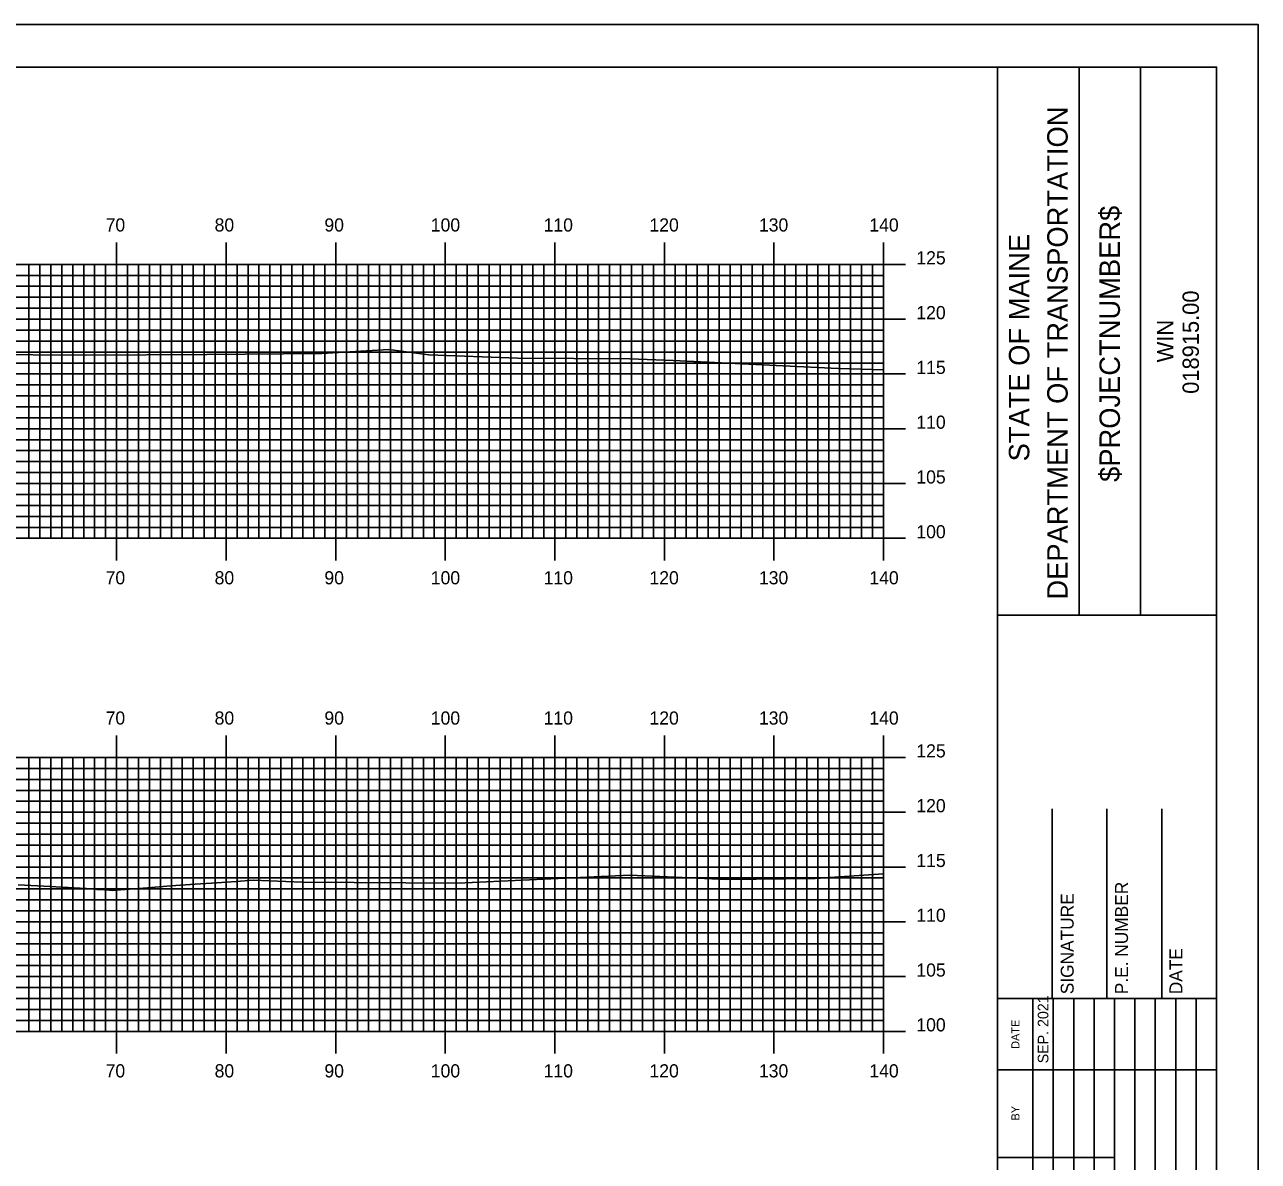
# Model space of a CAD drawing. Extents: x 1766513 to 1766856, y 442591 to 442811.
# Drawn here: x 1766740.5 to 1766853.1, y 442706.8 to 442810.5 of the extents above; entities that cross this region are included whole.
import ezdxf

# ---------------------------------------------------------------- set-up
doc = ezdxf.new("R2010")
doc.units = 0
for name, color, linetype in [('BORDER', 7, 'Continuous'), ('H_V ANNOTATION', 7, 'Continuous'), ('MAJOR', 7, 'Continuous'), ('MINOR', 7, 'Continuous'), ('PLOT BOUNDARY', 7, 'Continuous'), ('S_Roadway_Centerline', 7, 'Continuous')]:
    doc.layers.add(name, color=color, linetype=linetype)

msp = doc.modelspace()

# ---------------------------------------------------------------- linework, layer by layer
at = {"layer": 'BORDER'}
for p, q in [((1766829.31, 442596.67), (1766829.31, 442806.67)), ((1766836.77, 442756.66), (1766836.77, 442806.66)), ((1766842.36, 442756.66), (1766842.36, 442806.66)), ((1766829.31, 442756.65), (1766849.31, 442756.65)), ((1766834.31, 442721.67), (1766834.31, 442738.97)), ((1766839.31, 442721.67), (1766839.31, 442738.97)), ((1766844.31, 442721.67), (1766844.31, 442738.97)), ((1766829.31, 442721.67), (1766849.31, 442721.67))]:
    msp.add_line(p, q, dxfattribs=at)
msp.add_lwpolyline([(1766529.31, 442596.67), (1766849.31, 442596.67), (1766849.31, 442806.67), (1766529.31, 442806.67)], close=True, dxfattribs=at)
for points in [[(1766832.54, 442715.17), (1766832.54, 442721.67)], [(1766834.41, 442686.68), (1766834.41, 442721.67)], [(1766836.27, 442721.67), (1766836.27, 442686.68)], [(1766838.13, 442686.68), (1766838.13, 442721.67)], [(1766840, 442686.68), (1766840, 442721.67)], [(1766841.86, 442686.68), (1766841.86, 442721.67)], [(1766843.72, 442686.68), (1766843.72, 442721.67)], [(1766845.59, 442686.68), (1766845.59, 442721.67)], [(1766847.45, 442686.68), (1766847.45, 442721.67)], [(1766832.54, 442686.68), (1766832.54, 442720.26)], [(1766829.31, 442715.17), (1766849.31, 442715.17)], [(1766829.31, 442707.17), (1766832.54, 442707.17)], [(1766832.54, 442707.17), (1766839.99, 442707.17)]]:
    msp.add_lwpolyline(points, dxfattribs=at)
at = {"layer": 'MAJOR'}
for p, q in [((1766748.91, 442790.67), (1766748.91, 442788.67)), ((1766758.91, 442790.67), (1766758.91, 442788.67)), ((1766768.91, 442790.67), (1766768.91, 442788.67)), ((1766778.91, 442790.67), (1766778.91, 442788.67)), ((1766788.91, 442790.67), (1766788.91, 442788.67)), ((1766798.91, 442790.67), (1766798.91, 442788.67)), ((1766808.91, 442790.67), (1766808.91, 442788.67)), ((1766818.91, 442790.67), (1766818.91, 442788.67)), ((1766538.91, 442788.67), (1766818.91, 442788.67)), ((1766538.91, 442788.67), (1766818.91, 442788.67)), ((1766748.91, 442763.67), (1766748.91, 442788.67)), ((1766758.91, 442763.67), (1766758.91, 442788.67)), ((1766768.91, 442763.67), (1766768.91, 442788.67)), ((1766778.91, 442763.67), (1766778.91, 442788.67)), ((1766788.91, 442763.67), (1766788.91, 442788.67)), ((1766798.91, 442763.67), (1766798.91, 442788.67)), ((1766808.91, 442763.67), (1766808.91, 442788.67)), ((1766820.91, 442788.67), (1766816.91, 442788.67)), ((1766818.91, 442763.67), (1766818.91, 442788.67)), ((1766818.91, 442763.67), (1766818.91, 442788.67)), ((1766538.91, 442783.67), (1766818.91, 442783.67)), ((1766820.91, 442783.67), (1766816.91, 442783.67)), ((1766538.91, 442778.67), (1766818.91, 442778.67)), ((1766820.91, 442778.67), (1766816.91, 442778.67)), ((1766538.91, 442773.67), (1766818.91, 442773.67)), ((1766820.91, 442773.67), (1766816.91, 442773.67)), ((1766538.91, 442768.67), (1766818.91, 442768.67)), ((1766820.91, 442768.67), (1766816.91, 442768.67)), ((1766538.91, 442763.67), (1766818.91, 442763.67)), ((1766538.91, 442763.67), (1766818.91, 442763.67)), ((1766748.91, 442761.66), (1766748.91, 442763.67)), ((1766758.91, 442761.66), (1766758.91, 442763.67)), ((1766768.91, 442761.66), (1766768.91, 442763.67)), ((1766778.91, 442761.66), (1766778.91, 442763.67)), ((1766788.91, 442761.66), (1766788.91, 442763.67)), ((1766798.91, 442761.66), (1766798.91, 442763.67)), ((1766808.91, 442761.66), (1766808.91, 442763.67)), ((1766820.91, 442763.67), (1766816.91, 442763.67)), ((1766818.91, 442761.66), (1766818.91, 442763.67)), ((1766748.91, 442745.67), (1766748.91, 442743.67)), ((1766758.91, 442745.67), (1766758.91, 442743.67)), ((1766768.91, 442745.67), (1766768.91, 442743.67)), ((1766778.91, 442745.67), (1766778.91, 442743.67)), ((1766788.91, 442745.67), (1766788.91, 442743.67)), ((1766798.91, 442745.67), (1766798.91, 442743.67)), ((1766808.91, 442745.67), (1766808.91, 442743.67)), ((1766818.91, 442745.67), (1766818.91, 442743.67)), ((1766538.91, 442743.67), (1766818.91, 442743.67)), ((1766538.91, 442743.67), (1766818.91, 442743.67)), ((1766748.91, 442718.67), (1766748.91, 442743.67)), ((1766758.91, 442718.67), (1766758.91, 442743.67)), ((1766768.91, 442718.67), (1766768.91, 442743.67)), ((1766778.91, 442718.67), (1766778.91, 442743.67)), ((1766788.91, 442718.67), (1766788.91, 442743.67)), ((1766798.91, 442718.67), (1766798.91, 442743.67)), ((1766808.91, 442718.67), (1766808.91, 442743.67)), ((1766820.91, 442743.67), (1766816.91, 442743.67)), ((1766818.91, 442718.67), (1766818.91, 442743.67)), ((1766818.91, 442718.67), (1766818.91, 442743.67)), ((1766538.91, 442738.67), (1766818.91, 442738.67)), ((1766820.91, 442738.67), (1766816.91, 442738.67)), ((1766538.91, 442733.67), (1766818.91, 442733.67)), ((1766820.91, 442733.67), (1766816.91, 442733.67)), ((1766538.91, 442728.67), (1766818.91, 442728.67)), ((1766820.91, 442728.67), (1766816.91, 442728.67)), ((1766538.91, 442723.67), (1766818.91, 442723.67)), ((1766820.91, 442723.67), (1766816.91, 442723.67)), ((1766538.91, 442718.67), (1766818.91, 442718.67)), ((1766538.91, 442718.67), (1766818.91, 442718.67)), ((1766748.91, 442716.66), (1766748.91, 442718.67)), ((1766758.91, 442716.66), (1766758.91, 442718.67)), ((1766768.91, 442716.66), (1766768.91, 442718.67)), ((1766778.91, 442716.66), (1766778.91, 442718.67)), ((1766788.91, 442716.66), (1766788.91, 442718.67)), ((1766798.91, 442716.66), (1766798.91, 442718.67)), ((1766808.91, 442716.66), (1766808.91, 442718.67)), ((1766820.91, 442718.67), (1766816.91, 442718.67)), ((1766818.91, 442716.66), (1766818.91, 442718.67))]:
    msp.add_line(p, q, dxfattribs=at)
at = {"layer": 'MINOR'}
for p, q in [((1766740.91, 442763.67), (1766740.91, 442788.67)), ((1766741.91, 442763.67), (1766741.91, 442788.67)), ((1766742.91, 442763.67), (1766742.91, 442788.67)), ((1766743.91, 442763.67), (1766743.91, 442788.67)), ((1766744.91, 442763.67), (1766744.91, 442788.67)), ((1766745.91, 442763.67), (1766745.91, 442788.67)), ((1766746.91, 442763.67), (1766746.91, 442788.67)), ((1766747.91, 442763.67), (1766747.91, 442788.67)), ((1766749.91, 442763.67), (1766749.91, 442788.67)), ((1766750.91, 442763.67), (1766750.91, 442788.67)), ((1766751.91, 442763.67), (1766751.91, 442788.67)), ((1766752.91, 442763.67), (1766752.91, 442788.67)), ((1766753.91, 442763.67), (1766753.91, 442788.67)), ((1766754.91, 442763.67), (1766754.91, 442788.67)), ((1766755.91, 442763.67), (1766755.91, 442788.67)), ((1766756.91, 442763.67), (1766756.91, 442788.67)), ((1766757.91, 442763.67), (1766757.91, 442788.67)), ((1766759.91, 442763.67), (1766759.91, 442788.67)), ((1766760.91, 442763.67), (1766760.91, 442788.67)), ((1766761.91, 442763.67), (1766761.91, 442788.67)), ((1766762.91, 442763.67), (1766762.91, 442788.67)), ((1766763.91, 442763.67), (1766763.91, 442788.67)), ((1766764.91, 442763.67), (1766764.91, 442788.67)), ((1766765.91, 442763.67), (1766765.91, 442788.67)), ((1766766.91, 442763.67), (1766766.91, 442788.67)), ((1766767.91, 442763.67), (1766767.91, 442788.67)), ((1766769.91, 442763.67), (1766769.91, 442788.67)), ((1766770.91, 442763.67), (1766770.91, 442788.67)), ((1766771.91, 442763.67), (1766771.91, 442788.67)), ((1766772.91, 442763.67), (1766772.91, 442788.67)), ((1766773.91, 442763.67), (1766773.91, 442788.67)), ((1766774.91, 442763.67), (1766774.91, 442788.67)), ((1766775.91, 442763.67), (1766775.91, 442788.67)), ((1766776.91, 442763.67), (1766776.91, 442788.67)), ((1766777.91, 442763.67), (1766777.91, 442788.67)), ((1766779.91, 442763.67), (1766779.91, 442788.67)), ((1766780.91, 442763.67), (1766780.91, 442788.67)), ((1766781.91, 442763.67), (1766781.91, 442788.67)), ((1766782.91, 442763.67), (1766782.91, 442788.67)), ((1766783.91, 442763.67), (1766783.91, 442788.67)), ((1766784.91, 442763.67), (1766784.91, 442788.67)), ((1766785.91, 442763.67), (1766785.91, 442788.67)), ((1766786.91, 442763.67), (1766786.91, 442788.67)), ((1766787.91, 442763.67), (1766787.91, 442788.67)), ((1766789.91, 442763.67), (1766789.91, 442788.67)), ((1766790.91, 442763.67), (1766790.91, 442788.67)), ((1766791.91, 442763.67), (1766791.91, 442788.67)), ((1766792.91, 442763.67), (1766792.91, 442788.67)), ((1766793.91, 442763.67), (1766793.91, 442788.67)), ((1766794.91, 442763.67), (1766794.91, 442788.67)), ((1766795.91, 442763.67), (1766795.91, 442788.67)), ((1766796.91, 442763.67), (1766796.91, 442788.67)), ((1766797.91, 442763.67), (1766797.91, 442788.67)), ((1766799.91, 442763.67), (1766799.91, 442788.67)), ((1766800.91, 442763.67), (1766800.91, 442788.67)), ((1766801.91, 442763.67), (1766801.91, 442788.67)), ((1766802.91, 442763.67), (1766802.91, 442788.67)), ((1766803.91, 442763.67), (1766803.91, 442788.67)), ((1766804.91, 442763.67), (1766804.91, 442788.67)), ((1766805.91, 442763.67), (1766805.91, 442788.67)), ((1766806.91, 442763.67), (1766806.91, 442788.67)), ((1766807.91, 442763.67), (1766807.91, 442788.67)), ((1766809.91, 442763.67), (1766809.91, 442788.67)), ((1766810.91, 442763.67), (1766810.91, 442788.67)), ((1766811.91, 442763.67), (1766811.91, 442788.67)), ((1766812.91, 442763.67), (1766812.91, 442788.67)), ((1766813.91, 442763.67), (1766813.91, 442788.67)), ((1766814.91, 442763.67), (1766814.91, 442788.67)), ((1766815.91, 442763.67), (1766815.91, 442788.67)), ((1766816.91, 442763.67), (1766816.91, 442788.67)), ((1766817.91, 442763.67), (1766817.91, 442788.67)), ((1766538.91, 442787.67), (1766818.91, 442787.67)), ((1766818.91, 442787.67), (1766816.91, 442787.67)), ((1766538.91, 442786.67), (1766818.91, 442786.67)), ((1766818.91, 442786.67), (1766816.91, 442786.67)), ((1766538.91, 442785.67), (1766818.91, 442785.67)), ((1766818.91, 442785.67), (1766816.91, 442785.67)), ((1766538.91, 442784.67), (1766818.91, 442784.67)), ((1766818.91, 442784.67), (1766816.91, 442784.67)), ((1766538.91, 442782.67), (1766818.91, 442782.67)), ((1766818.91, 442782.67), (1766816.91, 442782.67)), ((1766538.91, 442781.67), (1766818.91, 442781.67)), ((1766818.91, 442781.67), (1766816.91, 442781.67)), ((1766538.91, 442780.67), (1766818.91, 442780.67)), ((1766538.91, 442779.67), (1766818.91, 442779.67)), ((1766818.91, 442780.67), (1766816.91, 442780.67)), ((1766818.91, 442779.67), (1766816.91, 442779.67)), ((1766538.91, 442777.67), (1766818.91, 442777.67)), ((1766818.91, 442777.67), (1766816.91, 442777.67)), ((1766538.91, 442776.67), (1766818.91, 442776.67)), ((1766818.91, 442776.67), (1766816.91, 442776.67)), ((1766538.91, 442775.67), (1766818.91, 442775.67)), ((1766818.91, 442775.67), (1766816.91, 442775.67)), ((1766538.91, 442774.67), (1766818.91, 442774.67)), ((1766818.91, 442774.67), (1766816.91, 442774.67)), ((1766538.91, 442772.67), (1766818.91, 442772.67)), ((1766818.91, 442772.67), (1766816.91, 442772.67)), ((1766538.91, 442771.67), (1766818.91, 442771.67)), ((1766538.91, 442770.67), (1766818.91, 442770.67)), ((1766818.91, 442771.67), (1766816.91, 442771.67)), ((1766818.91, 442770.67), (1766816.91, 442770.67)), ((1766538.91, 442769.67), (1766818.91, 442769.67)), ((1766818.91, 442769.67), (1766816.91, 442769.67)), ((1766538.91, 442767.67), (1766818.91, 442767.67)), ((1766818.91, 442767.67), (1766816.91, 442767.67)), ((1766538.91, 442766.67), (1766818.91, 442766.67)), ((1766818.91, 442766.67), (1766816.91, 442766.67)), ((1766538.91, 442765.67), (1766818.91, 442765.67)), ((1766818.91, 442765.67), (1766816.91, 442765.67)), ((1766538.91, 442764.67), (1766818.91, 442764.67)), ((1766818.91, 442764.67), (1766816.91, 442764.67)), ((1766740.91, 442718.67), (1766740.91, 442743.67)), ((1766741.91, 442718.67), (1766741.91, 442743.67)), ((1766742.91, 442718.67), (1766742.91, 442743.67)), ((1766743.91, 442718.67), (1766743.91, 442743.67)), ((1766744.91, 442718.67), (1766744.91, 442743.67)), ((1766745.91, 442718.67), (1766745.91, 442743.67)), ((1766746.91, 442718.67), (1766746.91, 442743.67)), ((1766747.91, 442718.67), (1766747.91, 442743.67)), ((1766749.91, 442718.67), (1766749.91, 442743.67)), ((1766750.91, 442718.67), (1766750.91, 442743.67)), ((1766751.91, 442718.67), (1766751.91, 442743.67)), ((1766752.91, 442718.67), (1766752.91, 442743.67)), ((1766753.91, 442718.67), (1766753.91, 442743.67)), ((1766754.91, 442718.67), (1766754.91, 442743.67)), ((1766755.91, 442718.67), (1766755.91, 442743.67)), ((1766756.91, 442718.67), (1766756.91, 442743.67)), ((1766757.91, 442718.67), (1766757.91, 442743.67)), ((1766759.91, 442718.67), (1766759.91, 442743.67)), ((1766760.91, 442718.67), (1766760.91, 442743.67)), ((1766761.91, 442718.67), (1766761.91, 442743.67)), ((1766762.91, 442718.67), (1766762.91, 442743.67)), ((1766763.91, 442718.67), (1766763.91, 442743.67)), ((1766764.91, 442718.67), (1766764.91, 442743.67)), ((1766765.91, 442718.67), (1766765.91, 442743.67)), ((1766766.91, 442718.67), (1766766.91, 442743.67)), ((1766767.91, 442718.67), (1766767.91, 442743.67)), ((1766769.91, 442718.67), (1766769.91, 442743.67)), ((1766770.91, 442718.67), (1766770.91, 442743.67)), ((1766771.91, 442718.67), (1766771.91, 442743.67)), ((1766772.91, 442718.67), (1766772.91, 442743.67)), ((1766773.91, 442718.67), (1766773.91, 442743.67)), ((1766774.91, 442718.67), (1766774.91, 442743.67)), ((1766775.91, 442718.67), (1766775.91, 442743.67)), ((1766776.91, 442718.67), (1766776.91, 442743.67)), ((1766777.91, 442718.67), (1766777.91, 442743.67)), ((1766779.91, 442718.67), (1766779.91, 442743.67)), ((1766780.91, 442718.67), (1766780.91, 442743.67)), ((1766781.91, 442718.67), (1766781.91, 442743.67)), ((1766782.91, 442718.67), (1766782.91, 442743.67)), ((1766783.91, 442718.67), (1766783.91, 442743.67)), ((1766784.91, 442718.67), (1766784.91, 442743.67)), ((1766785.91, 442718.67), (1766785.91, 442743.67)), ((1766786.91, 442718.67), (1766786.91, 442743.67)), ((1766787.91, 442718.67), (1766787.91, 442743.67)), ((1766789.91, 442718.67), (1766789.91, 442743.67)), ((1766790.91, 442718.67), (1766790.91, 442743.67)), ((1766791.91, 442718.67), (1766791.91, 442743.67)), ((1766792.91, 442718.67), (1766792.91, 442743.67)), ((1766793.91, 442718.67), (1766793.91, 442743.67)), ((1766794.91, 442718.67), (1766794.91, 442743.67)), ((1766795.91, 442718.67), (1766795.91, 442743.67)), ((1766796.91, 442718.67), (1766796.91, 442743.67)), ((1766797.91, 442718.67), (1766797.91, 442743.67)), ((1766799.91, 442718.67), (1766799.91, 442743.67)), ((1766800.91, 442718.67), (1766800.91, 442743.67)), ((1766801.91, 442718.67), (1766801.91, 442743.67)), ((1766802.91, 442718.67), (1766802.91, 442743.67)), ((1766803.91, 442718.67), (1766803.91, 442743.67)), ((1766804.91, 442718.67), (1766804.91, 442743.67)), ((1766805.91, 442718.67), (1766805.91, 442743.67)), ((1766806.91, 442718.67), (1766806.91, 442743.67)), ((1766807.91, 442718.67), (1766807.91, 442743.67)), ((1766809.91, 442718.67), (1766809.91, 442743.67)), ((1766810.91, 442718.67), (1766810.91, 442743.67)), ((1766811.91, 442718.67), (1766811.91, 442743.67)), ((1766812.91, 442718.67), (1766812.91, 442743.67)), ((1766813.91, 442718.67), (1766813.91, 442743.67)), ((1766814.91, 442718.67), (1766814.91, 442743.67)), ((1766815.91, 442718.67), (1766815.91, 442743.67)), ((1766816.91, 442718.67), (1766816.91, 442743.67)), ((1766817.91, 442718.67), (1766817.91, 442743.67)), ((1766538.91, 442742.67), (1766818.91, 442742.67)), ((1766818.91, 442742.67), (1766816.91, 442742.67)), ((1766538.91, 442741.67), (1766818.91, 442741.67)), ((1766818.91, 442741.67), (1766816.91, 442741.67)), ((1766538.91, 442740.67), (1766818.91, 442740.67)), ((1766818.91, 442740.67), (1766816.91, 442740.67)), ((1766538.91, 442739.67), (1766818.91, 442739.67)), ((1766818.91, 442739.67), (1766816.91, 442739.67)), ((1766538.91, 442737.67), (1766818.91, 442737.67)), ((1766818.91, 442737.67), (1766816.91, 442737.67)), ((1766538.91, 442736.67), (1766818.91, 442736.67)), ((1766818.91, 442736.67), (1766816.91, 442736.67)), ((1766538.91, 442735.67), (1766818.91, 442735.67)), ((1766538.91, 442734.67), (1766818.91, 442734.67)), ((1766818.91, 442735.67), (1766816.91, 442735.67)), ((1766818.91, 442734.67), (1766816.91, 442734.67)), ((1766538.91, 442732.67), (1766818.91, 442732.67)), ((1766818.91, 442732.67), (1766816.91, 442732.67)), ((1766538.91, 442731.67), (1766818.91, 442731.67)), ((1766818.91, 442731.67), (1766816.91, 442731.67)), ((1766538.91, 442730.67), (1766818.91, 442730.67)), ((1766818.91, 442730.67), (1766816.91, 442730.67)), ((1766538.91, 442729.67), (1766818.91, 442729.67)), ((1766818.91, 442729.67), (1766816.91, 442729.67)), ((1766538.91, 442727.67), (1766818.91, 442727.67)), ((1766538.91, 442726.67), (1766818.91, 442726.67)), ((1766818.91, 442727.67), (1766816.91, 442727.67)), ((1766818.91, 442726.67), (1766816.91, 442726.67)), ((1766538.91, 442725.67), (1766818.91, 442725.67)), ((1766818.91, 442725.67), (1766816.91, 442725.67)), ((1766538.91, 442724.67), (1766818.91, 442724.67)), ((1766818.91, 442724.67), (1766816.91, 442724.67)), ((1766538.91, 442722.67), (1766818.91, 442722.67)), ((1766818.91, 442722.67), (1766816.91, 442722.67)), ((1766538.91, 442721.67), (1766818.91, 442721.67)), ((1766818.91, 442721.67), (1766816.91, 442721.67)), ((1766538.91, 442720.67), (1766818.91, 442720.67)), ((1766818.91, 442720.67), (1766816.91, 442720.67)), ((1766538.91, 442719.67), (1766818.91, 442719.67)), ((1766818.91, 442719.67), (1766816.91, 442719.67))]:
    msp.add_line(p, q, dxfattribs=at)
at = {"layer": 'PLOT BOUNDARY'}
msp.add_lwpolyline([(1766513.12, 442590.55), (1766853.12, 442590.55), (1766853.12, 442810.55), (1766513.12, 442810.55)], close=True, dxfattribs=at)
at = {"layer": 'S_Roadway_Centerline'}
for points in [[(1766736.42, 442780.44), (1766746.09, 442780.38), (1766757.14, 442780.44), (1766767.66, 442780.55), (1766773.77, 442780.89), (1766777.42, 442780.43), (1766785.55, 442780.12), (1766795.75, 442780.04), (1766799.72, 442779.9), (1766814.78, 442779.18), (1766818.91, 442779.05)], [(1766739.94, 442732.05), (1766742.27, 442731.91), (1766746.7, 442731.67), (1766747.11, 442731.63), (1766747.8, 442731.6), (1766748.27, 442731.56), (1766748.54, 442731.53), (1766748.87, 442731.56), (1766751.72, 442731.78), (1766753.85, 442731.94), (1766756.08, 442732.1), (1766758.07, 442732.24), (1766759.83, 442732.36), (1766761.38, 442732.47), (1766765.84, 442732.29), (1766780.06, 442732.21), (1766795.75, 442732.94), (1766804.6, 442732.52), (1766812.66, 442732.62), (1766818.91, 442733.06)]]:
    msp.add_lwpolyline(points, dxfattribs=at)

# ---------------------------------------------------------------- texts
at = {"layer": 'BORDER'}
for s, height, p in [('DEPARTMENT OF TRANSPORTATION', 1.8635, (1766835.72, 442758.08)), ('$PROJECTNUMBER$', 1.8635, (1766840.49, 442768.82)), ('STATE OF MAINE', 1.8635, (1766832.22, 442770.69)), ('018915.00', 1.491, (1766847.7, 442776.86)), ('WIN', 1.491, (1766845.38, 442779.73)), ('SIGNATURE', 1.181, (1766836.27, 442722.06)), ('P.E. NUMBER', 1.1811, (1766841.23, 442722.06)), ('DATE', 1.181, (1766846.19, 442722.06)), ('SEP. 2021', 0.969, (1766833.96, 442715.76)), ('DATE', 0.743, (1766831.32, 442717.08)), ('BY', 0.743, (1766831.32, 442710.54))]:
    msp.add_text(s, height=height, rotation=90, dxfattribs=at).set_placement(p)
at = {"layer": 'H_V ANNOTATION'}
for s, p in [('70', (1766747.91, 442791.67)), ('80', (1766757.86, 442791.67)), ('90', (1766767.88, 442791.67)), ('100', (1766777.59, 442791.67)), ('110', (1766787.89, 442791.67)), ('120', (1766797.55, 442791.67)), ('130', (1766807.54, 442791.67)), ('140', (1766817.62, 442791.67)), ('125', (1766821.91, 442788.67)), ('120', (1766821.91, 442783.67)), ('115', (1766821.91, 442778.67)), ('110', (1766821.91, 442773.67)), ('105', (1766821.91, 442768.67)), ('100', (1766821.91, 442763.67)), ('70', (1766747.91, 442759.47)), ('80', (1766757.86, 442759.47)), ('90', (1766767.88, 442759.47)), ('100', (1766777.59, 442759.47)), ('110', (1766787.89, 442759.47)), ('120', (1766797.55, 442759.47)), ('130', (1766807.54, 442759.47)), ('140', (1766817.62, 442759.47)), ('70', (1766747.91, 442746.67)), ('80', (1766757.86, 442746.67)), ('90', (1766767.88, 442746.67)), ('100', (1766777.59, 442746.67)), ('110', (1766787.89, 442746.67)), ('120', (1766797.55, 442746.67)), ('130', (1766807.54, 442746.67)), ('140', (1766817.62, 442746.67)), ('125', (1766821.91, 442743.67)), ('120', (1766821.91, 442738.67)), ('115', (1766821.91, 442733.67)), ('110', (1766821.91, 442728.67)), ('105', (1766821.91, 442723.67)), ('100', (1766821.91, 442718.67)), ('70', (1766747.91, 442714.47)), ('80', (1766757.86, 442714.47)), ('90', (1766767.88, 442714.47)), ('100', (1766777.59, 442714.47)), ('110', (1766787.89, 442714.47)), ('120', (1766797.55, 442714.47)), ('130', (1766807.54, 442714.47)), ('140', (1766817.62, 442714.47))]:
    msp.add_text(s, height=1.2, dxfattribs=at).set_placement(p)

doc.saveas('drawing.dxf')
